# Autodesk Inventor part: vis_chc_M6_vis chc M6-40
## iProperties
Shininess: 64.0
Length Units: 11269
Angle Units: 11279
Time Units: 11290
Mass Units: 11283
Length Display Precision: 3
Angle Display Precision: 2
Compacted: True
Part Number: vis_chc_M6_vis chc M6-40
Document SubType Name: Modeling
Created: 2006-01
Material: Par défaut
Designer: riri
Density: 0.0
Volumn: 0.0
Area: 0.0
PropertySet Name: Model Information
Control State: 0
Master: False
Checked Out: False
Author: riri
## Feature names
1. Base1
